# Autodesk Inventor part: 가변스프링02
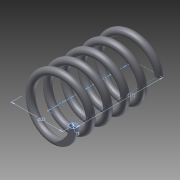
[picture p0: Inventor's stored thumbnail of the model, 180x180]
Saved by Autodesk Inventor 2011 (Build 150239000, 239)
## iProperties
Created: 2015-05
Part Number: 가변스프링02
Material: 탄소강
Document SubType Name: Modeling
Designer: Administrator
Mass: 18.8475 g
Surface Area: 32.4803 cm^2
Volume: 2.39485 cm^3
Density: 7.87 g/cm^3
Author: Administrator
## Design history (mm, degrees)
sketch "스케치1"
  geometry: L1 (0, 0)-(11, 0); L2 (11, 0)-(11, 36.411); L3 (11, 36.411)-(0, 36.411); L4 (0, 36.411)-(0, 0); C1 r 1.5 at (11, 0); 1 further point
  constraints: 8 end point, 2 coincident, 2 parallel, 1 centre point, 1 horizontal, 1 perpendicular
  dimensions: "d0" = 36.4112 distance of L1.end L2.end (derived); "d1" = 22 diameter of L2 L4; "d2" = 3 diameter of C1
feature "코일1" sketch "스케치1" pitch "d3" = 10; turns "d5" = 5; dims "d4" = 36.4112 (= d0), "d6" = 0, angle "d7" = 90 deg, angle "d8" = 90 deg, "d9" = 0, "d10" = 0
sketch "스케치2"
  geometry: L1 (-12.5, 0)-(-9.5, 0) reference; 1 further point
  constraints: 1 horizontal alignment
extrude "돌출1" cut sketch "스케치2" stored distance "d11" = 10; taper "d12" = 0 deg
node "작업 평면1"
sketch "스케치3"
  geometry: L1 (1.5, 0)-(-1.5, 0) reference; 1 further point
  constraints: 1 horizontal alignment
extrude "돌출2" cut sketch "스케치3" stored distance "d13" = 10; taper "d14" = 0 deg
node "솔리드1"
node "절단 모서리 투영1"
node "절단 모서리 투영2"
